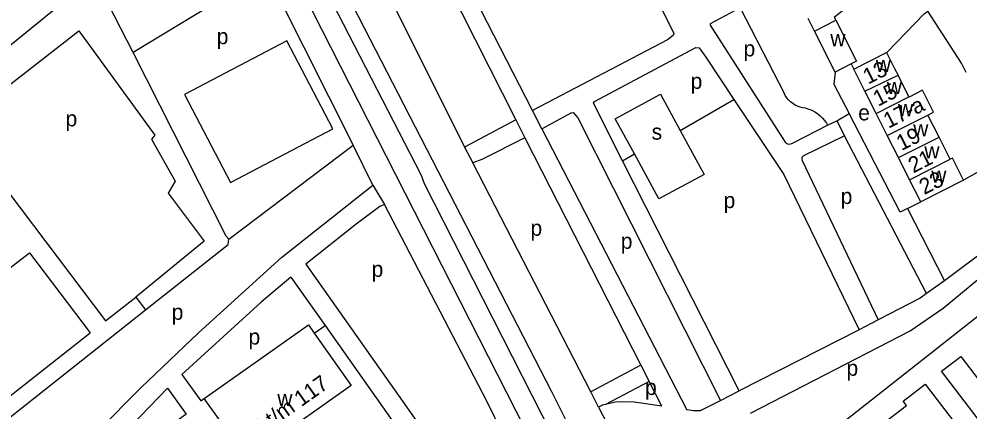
# Model space of a CAD drawing. Extents: x 158848 to 160613, y 385889 to 387762.
# Drawn here: x 159630.1 to 159871.5, y 386560.1 to 386659.8 of the extents above; entities that cross this region are included whole.
import ezdxf

# ---------------------------------------------------------------- set-up
doc = ezdxf.new("R2010")
doc.units = 0
for name, color, linetype in [('BLT_Basislijn', 7, 'Continuous'), ('BLT_Bebouwing', 7, 'Continuous'), ('BLT_Centroide', 7, 'Continuous'), ('BLT_Huisnummer', 7, 'Continuous'), ('BLT_Huisnummer_ tussenligend', 7, 'Continuous'), ('BLT_Huisnummer_reeks', 7, 'Continuous'), ('BLT_Huisnummer_zonder_bebouwing', 7, 'Continuous'), ('BLT_Onderverdeling_panden', 7, 'Continuous'), ('BLT_Vlakafsluiter', 7, 'Continuous')]:
    doc.layers.add(name, color=color, linetype=linetype)

msp = doc.modelspace()

# ---------------------------------------------------------------- linework, layer by layer
at = {"layer": 'BLT_Basislijn'}
for p, q in [((159760.56, 386636.47), (159705.82, 386743.7)), ((159692.82, 386671.75), (159659.12, 386651.22)), ((159692.82, 386671.75), (159715.04, 386627.72)), ((159813.37, 386662.62), (159824.62, 386640.76)), ((159698.17, 386654.19), (159672.14, 386640.6)), ((159709.85, 386631.81), (159698.17, 386654.19)), ((159841.57, 386648.35), (159842.23, 386647.02)), ((159672.14, 386640.6), (159683.82, 386618.22)), ((159762.99, 386631.83), (159760.56, 386636.47)), ((159837.94, 386633.84), (159841.03, 386635.75)), ((159756.34, 386634.13), (159743.32, 386627.14)), ((159756.34, 386634.13), (159758.6, 386629.58)), ((159835.55, 386632.78), (159837.94, 386633.84)), ((159837.94, 386633.84), (159839.86, 386630.08)), ((159614.48, 386632.78), (159652.08, 386583.03)), ((159683.82, 386618.22), (159709.85, 386631.81)), ((159762.99, 386631.83), (159799.81, 386560.41)), ((159827, 386628.37), (159835.55, 386632.78)), ((159758.6, 386629.58), (159788.12, 386571.71)), ((159839.86, 386630.08), (159829.5, 386624.98)), ((159860.71, 386589.94), (159839.86, 386630.08)), ((159683.4, 386603.77), (159715.04, 386627.72)), ((159743.32, 386627.14), (159745.39, 386623.16)), ((159883.58, 386626.46), (159870.14, 386618.76)), ((159829.13, 386623.8), (159848.43, 386583.24)), ((159775.44, 386564.95), (159745.39, 386623.16)), ((159855.85, 386611.57), (159859.29, 386613.28)), ((159855.85, 386611.57), (159865.31, 386593.16)), ((159891.89, 386613.25), (159865.31, 386593.16)), ((159597.32, 386573.15), (159632.73, 386600.34)), ((159632.73, 386600.34), (159648.15, 386579.94)), ((159702.98, 386597.45), (159740.62, 386544.15)), ((159699.2, 386594.13), (159707.9, 386581.81)), ((159865.31, 386593.16), (159860.71, 386589.94)), ((159652.08, 386583.03), (159659.74, 386589.06)), ((159659.74, 386589.06), (159662.24, 386585.81)), ((159619.58, 386552.04), (159662.24, 386585.81)), ((159848.43, 386583.24), (159843.63, 386580.77)), ((159613.45, 386552.66), (159648.15, 386579.94)), ((159705.13, 386579.87), (159707.9, 386581.81)), ((159707.9, 386581.81), (159732.56, 386546.9)), ((159843.63, 386580.77), (159813.08, 386565.22)), ((159788.12, 386571.71), (159775.44, 386564.95)), ((159788.12, 386571.71), (159790.27, 386567.56)), ((159790.27, 386567.56), (159779.16, 386561.76)), ((159793.42, 386561.35), (159790.27, 386567.56)), ((159777.4, 386561.1), (159775.44, 386564.95)), ((159808.39, 386562.78), (159813.08, 386565.22)), ((159777.4, 386561.1), (159779.63, 386556.62)), ((159803.09, 386560.16), (159808.39, 386562.78))]:
    msp.add_line(p, q, dxfattribs=at)
for points in [[(159680.55, 386782.68), (159719.19, 386707.16), (159721.99, 386702.16), (159756.34, 386634.13)], [(159669.84, 386771.09), (159692.47, 386727.87), (159726.01, 386661.88), (159743.32, 386627.14)], [(159653.96, 386761.48), (159688.89, 386693.23), (159690.55, 386689.53), (159763.39, 386546.32)], [(159660.24, 386760.04), (159732.27, 386620.02), (159733.09, 386617.95), (159765.38, 386554.25)], [(159705.82, 386743.7), (159727.46, 386754.76), (159730.32, 386754.06), (159731.69, 386753.2), (159786.89, 386672.71), (159792.62, 386663.96), (159796.5, 386656.07), (159796.34, 386655.59), (159794.91, 386654.47), (159760.56, 386636.47)], [(159668.69, 386753.01), (159765.45, 386565.06), (159769.44, 386557.1)], [(159659.12, 386651.22), (159649.43, 386670.19), (159648.56, 386670), (159631.81, 386656.29)], [(159813.37, 386662.62), (159805.73, 386658.55), (159805.73, 386658.23), (159824.77, 386628.41)], [(159850.57, 386651.23), (159850.75, 386651.31), (159860.11, 386661.11), (159861.05, 386661.75)], [(159870.83, 386646.16), (159869.62, 386648.54), (159861.05, 386661.75)], [(159631.81, 386656.29), (159601.65, 386631.78)], [(159614.48, 386632.78), (159645.31, 386656.72), (159664.62, 386630.27), (159663.76, 386629.25), (159669.81, 386618.52), (159668.03, 386615.51), (159677.14, 386603.26), (159659.74, 386589.06)], [(159783.48, 386623.7), (159776.06, 386638.38), (159776.33, 386638.78), (159802.07, 386652.5), (159802.93, 386652.41), (159804.62, 386650.02), (159811.75, 386639.34)], [(159683.4, 386603.77), (159682.76, 386604.52), (159659.12, 386651.22)], [(159837.49, 386646.27), (159837.15, 386643.18), (159841.03, 386635.75)], [(159786.49, 386625.46), (159781.63, 386634.4), (159793.1, 386640.63)], [(159793.1, 386640.63), (159798.1, 386631.42)], [(159830.02, 386637.13), (159829.32, 386637.21), (159828.62, 386637.36), (159827.96, 386637.59), (159827.32, 386637.89), (159826.71, 386638.26), (159826.16, 386638.7), (159825.66, 386639.2), (159825.21, 386639.75), (159824.83, 386640.35), (159824.62, 386640.76)], [(159811.75, 386639.34), (159824.5, 386620.27), (159843.63, 386580.77)], [(159762.99, 386631.83), (159770.41, 386635.91), (159770.89, 386635.96), (159772.07, 386634.65), (159808.39, 386562.78)], [(159830.02, 386637.13), (159830.82, 386636.88), (159831.59, 386636.56), (159832.33, 386636.16), (159833.03, 386635.7), (159833.68, 386635.17), (159834.28, 386634.58), (159834.81, 386633.94), (159835.29, 386633.24), (159835.55, 386632.78)], [(159855.85, 386611.57), (159854.03, 386610.67), (159841.03, 386635.75)], [(159798.1, 386631.42), (159804.18, 386620.25), (159792.71, 386614.02), (159786.49, 386625.46)], [(159758.6, 386629.58), (159747.73, 386624.03), (159745.39, 386623.16)], [(159824.77, 386628.41), (159825.07, 386628.19), (159825.41, 386628.05), (159825.77, 386627.98), (159826.14, 386627.99), (159826.5, 386628.08), (159826.83, 386628.24), (159827, 386628.37)], [(159720.05, 386617.5), (159715.04, 386627.72)], [(159813.08, 386565.22), (159783.48, 386623.7)], [(159829.5, 386624.98), (159829.29, 386624.82), (159829.13, 386624.6), (159829.05, 386624.35), (159829.04, 386624.09), (159829.13, 386623.8)], [(159573.48, 386514.55), (159589.7, 386503.28), (159591.03, 386503.75), (159608.94, 386517.82), (159624.63, 386531.34), (159650.13, 386554.93), (159661.12, 386566.05), (159675.68, 386579.96), (159696.76, 386599.11), (159720.05, 386617.5)], [(159740.62, 386544.15), (159753.12, 386553.55), (159753.02, 386554.25), (159749.1, 386562.43), (159722.94, 386612.64), (159721.82, 386612.11), (159715.8, 386607.62), (159702.98, 386597.45)], [(159816.01, 386559.58), (159856.57, 386580.44), (159864.97, 386586.23), (159880.09, 386598.8), (159895, 386609.89)], [(159662.24, 386585.81), (159683.28, 386602.47), (159683.4, 386603.77)], [(159913.33, 386568.72), (159913.75, 386569.78), (159891.93, 386598.06), (159885.42, 386593.32), (159833.17, 386552.18), (159833.33, 386550.75), (159852.66, 386513.61), (159854.09, 386514), (159867.93, 386521.11)], [(159699.2, 386594.13), (159691.64, 386587.79), (159671.49, 386569.36)], [(159860.71, 386589.94), (159859.12, 386588.82), (159848.43, 386583.24)], [(159671.49, 386569.36), (159676.27, 386562.66), (159677.18, 386563.31)], [(159667.79, 386565.93), (159654.28, 386551.87), (159657.05, 386547.95)], [(159667.79, 386565.93), (159672.53, 386559.29), (159657.05, 386547.95)], [(159779.16, 386561.76), (159778.37, 386561.57), (159777.4, 386561.1)], [(159793.42, 386561.35), (159786.43, 386562.37), (159781.92, 386562.42), (159779.16, 386561.76)], [(159803.09, 386560.16), (159801.49, 386560.16), (159799.81, 386560.41)]]:
    msp.add_lwpolyline(points, dxfattribs=at)
at = {"layer": 'BLT_Bebouwing'}
for p, q in [((159832.25, 386656.69), (159830.65, 386659.86)), ((159837.49, 386646.27), (159832.25, 386656.69)), ((159841.57, 386648.35), (159837.49, 386646.27)), ((159845.07, 386641.39), (159842.23, 386647.02)), ((159847.92, 386635.77), (159845.07, 386641.39)), ((159850.76, 386630.15), (159847.92, 386635.77)), ((159853.6, 386624.53), (159850.76, 386630.15)), ((159866.73, 386624.13), (159863.9, 386629.73)), ((159856.44, 386618.9), (159853.6, 386624.53)), ((159859.29, 386613.28), (159856.44, 386618.9)), ((159870.14, 386618.76), (159859.29, 386613.28)), ((159680.36, 386558.82), (159677.18, 386563.31))]:
    msp.add_line(p, q, dxfattribs=at)
for points in [[(159837.71, 386659.43), (159837.36, 386660.35), (159842.36, 386664.18)], [(159837.71, 386659.43), (159842.97, 386649.07), (159841.94, 386648.55), (159841.57, 386648.35)], [(159842.23, 386647.02), (159846.43, 386649.14), (159850.57, 386651.23)], [(159850.57, 386651.23), (159852.61, 386647.19), (159853.5, 386645.45)], [(159856.33, 386639.86), (159855.48, 386641.54), (159853.5, 386645.45)], [(159861.07, 386635.33), (159862.54, 386636.08), (159859.72, 386641.66), (159856.33, 386639.86)], [(159863.9, 386629.73), (159861.07, 386635.33)], [(159870.14, 386618.76), (159867.29, 386624.41), (159866.73, 386624.13)], [(159677.18, 386563.31), (159703.64, 386581.99), (159705.13, 386579.87)], [(159705.13, 386579.87), (159714.54, 386566.55), (159692.7, 386551.12), (159692.25, 386551.74), (159687.67, 386548.49), (159680.36, 386558.82)]]:
    msp.add_lwpolyline(points, dxfattribs=at)
for points in [[(159864.51, 386570.2), (159869.43, 386573.97), (159878.8, 386561.75), (159873.88, 386557.98)], [(159864.21, 386537.67), (159849.49, 386556.76), (159855.65, 386561.52), (159854.79, 386562.63), (159860.35, 386566.91), (159876.76, 386545.59), (159871.21, 386541.31), (159870.36, 386542.42)]]:
    msp.add_lwpolyline(points, close=True, dxfattribs=at)
at = {"layer": 'BLT_Onderverdeling_panden'}
for p, q in [((159845.07, 386641.39), (159853.5, 386645.45)), ((159850.76, 386630.15), (159861.07, 386635.33)), ((159853.6, 386624.53), (159863.9, 386629.73)), ((159856.44, 386618.9), (159866.73, 386624.13))]:
    msp.add_line(p, q, dxfattribs=at)
for points in [[(159832.25, 386656.69), (159837.71, 386659.43)], [(159847.92, 386635.77), (159856.26, 386639.99), (159856.33, 386639.86)]]:
    msp.add_lwpolyline(points, dxfattribs=at)
at = {"layer": 'BLT_Vlakafsluiter'}
for p, q in [((159798.1, 386631.42), (159811.75, 386639.34)), ((159783.48, 386623.7), (159786.49, 386625.46)), ((159720.05, 386617.5), (159722.94, 386612.64))]:
    msp.add_line(p, q, dxfattribs=at)

# ---------------------------------------------------------------- texts
at = {"layer": 'BLT_Centroide'}
for s, p in [('p', (159680.33, 386653.36)), ('w', (159836.28, 386652.84)), ('p', (159814.22, 386650.26)), ('w', (159847.82, 386646.31)), ('p', (159800.77, 386642)), ('w', (159850.63, 386640.69)), ('w', (159853.45, 386635.06)), ('p', (159641.91, 386632.46)), ('e', (159843.37, 386633.98)), ('w', (159857.34, 386629.94)), ('s', (159790.86, 386629.09)), ('w', (159860.17, 386624.31)), ('w', (159861.93, 386618.16)), ('p', (159809.15, 386611.68)), ('p', (159838.91, 386612.73)), ('p', (159760.07, 386604.65)), ('p', (159783.02, 386601.32)), ('p', (159719.7, 386594.2)), ('p', (159668.88, 386583.27)), ('p', (159688.41, 386576.98)), ('p', (159840.39, 386569.04)), ('p', (159789.19, 386564.16)), ('w', (159695.73, 386561.37))]:
    msp.add_text(s, height=4, dxfattribs=at).set_placement(p)
at = {"layer": 'BLT_Huisnummer'}
for s, rotation, p in [('13', 26.818, (159845.86, 386643.06)), ('23', 26.8012, (159860.14, 386615.01))]:
    msp.add_text(s, height=4, rotation=rotation, dxfattribs=at).set_placement(p)
at = {"layer": 'BLT_Huisnummer_ tussenligend'}
for s, rotation, p in [('15', 26.818, (159848.42, 386637.46)), ('19', 26.8151, (159854.34, 386626.17)), ('21', 26.8151, (159857.36, 386620.49))]:
    msp.add_text(s, height=4, rotation=rotation, dxfattribs=at).set_placement(p)
at = {"layer": 'BLT_Huisnummer_reeks'}
msp.add_text('17-a', height=4, rotation=26.8151, dxfattribs=at).set_placement((159851.06, 386631.86))
at = {"layer": 'BLT_Huisnummer_zonder_bebouwing'}
msp.add_text('57 t/m 117', height=4, rotation=35.2217, dxfattribs=at).set_placement((159688.46, 386551.63))

doc.saveas('drawing.dxf')
